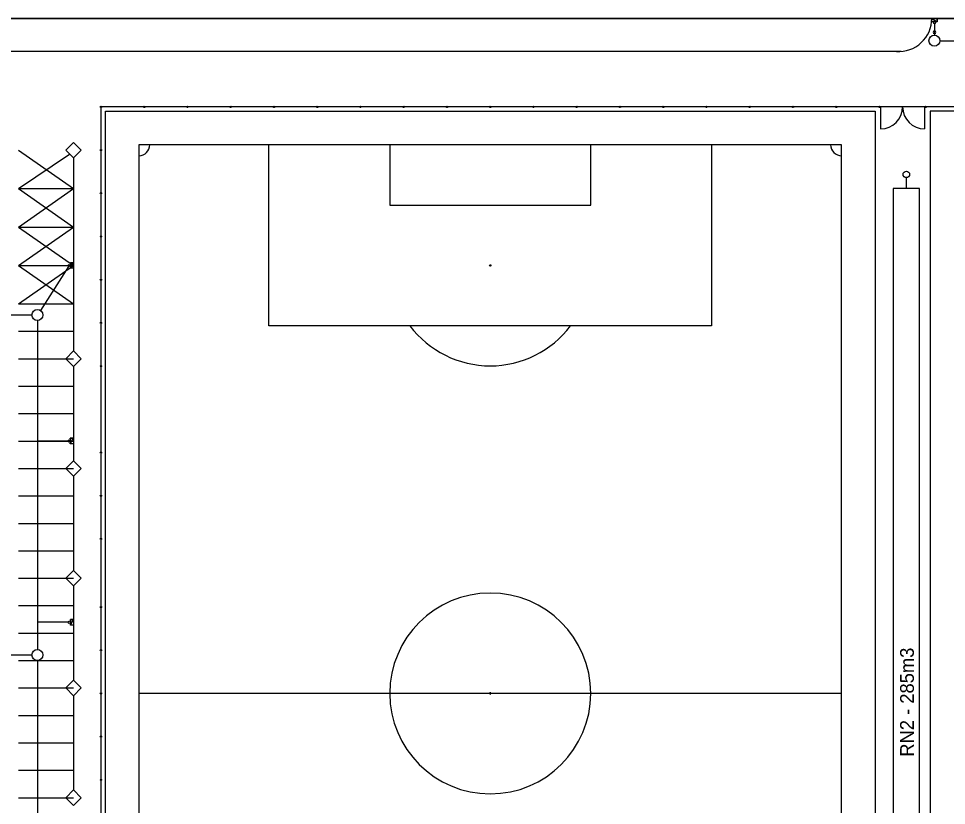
# Model space of a CAD drawing. Extents: x -264205 to -263615, y -1242401 to -1242031.
# Drawn here: x -264125.6 to -264041.1, y -1242251.2 to -1242179.5 of the extents above; entities that cross this region are included whole.
import ezdxf

# ---------------------------------------------------------------- set-up
doc = ezdxf.new("R2010")
doc.units = 0
doc.layers.add('KOORDINACNA_SITUACIA_DSP', color=7, linetype='Continuous')
doc.layers.add('PROJEKT_DRS_TDZ_VODOROVNE', color=7, linetype='Continuous')

msp = doc.modelspace()

# ---------------------------------------------------------------- linework, layer by layer
at = {"layer": 'KOORDINACNA_SITUACIA_DSP'}
for p, q in [((-264077.23, -1242179.482), (-264131.568, -1242179.482)), ((-264131.568, -1242179.482), (-263959.468, -1242179.482)), ((-263959.468, -1242179.482), (-264131.568, -1242179.482)), ((-263959.468, -1242179.482), (-264077.23, -1242179.482)), ((-264042.417, -1242179.482), (-264041.917, -1242179.482)), ((-264042.417, -1242179.772), (-264042.417, -1242179.482)), ((-264042.417, -1242179.482), (-264041.917, -1242179.772)), ((-264042.417, -1242179.482), (-264041.917, -1242179.772)), ((-264041.917, -1242179.482), (-264042.417, -1242179.482)), ((-264041.917, -1242179.482), (-264041.917, -1242179.772)), ((-264041.917, -1242179.772), (-264041.917, -1242179.482)), ((-264041.917, -1242179.772), (-264042.417, -1242179.772)), ((-264042.167, -1242179.972), (-264042.167, -1242181)), ((-264041.667, -1242181.5), (-264014.161, -1242181.5)), ((-264045.204, -1242182.482), (-264131.568, -1242182.482)), ((-264118.008, -1242187.532), (-264118.128, -1242187.532)), ((-264118.068, -1242187.592), (-264118.068, -1242187.472)), ((-263972.068, -1242187.532), (-264118.068, -1242187.532)), ((-264118.068, -1242187.532), (-264118.068, -1242294.432)), ((-264114.069, -1242187.532), (-264114.189, -1242187.532)), ((-264114.129, -1242187.592), (-264114.129, -1242187.472)), ((-264110.13, -1242187.532), (-264110.25, -1242187.532)), ((-264110.19, -1242187.592), (-264110.19, -1242187.472)), ((-264106.191, -1242187.532), (-264106.311, -1242187.532)), ((-264106.251, -1242187.592), (-264106.251, -1242187.472)), ((-264102.252, -1242187.532), (-264102.372, -1242187.532)), ((-264102.312, -1242187.592), (-264102.312, -1242187.472)), ((-264098.313, -1242187.532), (-264098.433, -1242187.532)), ((-264098.373, -1242187.592), (-264098.373, -1242187.472)), ((-264094.374, -1242187.532), (-264094.494, -1242187.532)), ((-264094.434, -1242187.592), (-264094.434, -1242187.472)), ((-264090.436, -1242187.532), (-264090.556, -1242187.532)), ((-264090.496, -1242187.592), (-264090.496, -1242187.472)), ((-264086.497, -1242187.532), (-264086.617, -1242187.532)), ((-264086.557, -1242187.592), (-264086.557, -1242187.472)), ((-264082.558, -1242187.532), (-264082.678, -1242187.532)), ((-264082.618, -1242187.592), (-264082.618, -1242187.472)), ((-264078.619, -1242187.532), (-264078.739, -1242187.532)), ((-264078.679, -1242187.592), (-264078.679, -1242187.472)), ((-264074.68, -1242187.532), (-264074.8, -1242187.532)), ((-264074.74, -1242187.592), (-264074.74, -1242187.472)), ((-264070.741, -1242187.532), (-264070.861, -1242187.532)), ((-264070.801, -1242187.592), (-264070.801, -1242187.472)), ((-264066.802, -1242187.532), (-264066.922, -1242187.532)), ((-264066.862, -1242187.592), (-264066.862, -1242187.472)), ((-264062.863, -1242187.532), (-264062.983, -1242187.532)), ((-264062.923, -1242187.592), (-264062.923, -1242187.472)), ((-264058.924, -1242187.532), (-264059.044, -1242187.532)), ((-264058.984, -1242187.592), (-264058.984, -1242187.472)), ((-264054.986, -1242187.532), (-264055.106, -1242187.532)), ((-264055.046, -1242187.592), (-264055.046, -1242187.472)), ((-264051.047, -1242187.532), (-264051.167, -1242187.532)), ((-264051.107, -1242187.592), (-264051.107, -1242187.472)), ((-264047.108, -1242187.532), (-264047.228, -1242187.532)), ((-264047.168, -1242187.592), (-264047.168, -1242187.472)), ((-264047.068, -1242187.532), (-264047.068, -1242189.532)), ((-264044.568, -1242187.532), (-264045.568, -1242187.532)), ((-264043.068, -1242187.532), (-264043.068, -1242189.532)), ((-264042.908, -1242187.532), (-264043.028, -1242187.532)), ((-264042.968, -1242187.592), (-264042.968, -1242187.472)), ((-264118.068, -1242191.41), (-264118.068, -1242191.53)), ((-264050.618, -1242190.982), (-264114.618, -1242190.982)), ((-264114.618, -1242190.982), (-264114.618, -1242290.982)), ((-264102.778, -1242207.482), (-264102.778, -1242190.982)), ((-264091.778, -1242190.982), (-264091.778, -1242196.482)), ((-264073.458, -1242196.482), (-264073.458, -1242190.982)), ((-264062.458, -1242190.982), (-264062.458, -1242207.482)), ((-264050.618, -1242290.982), (-264050.618, -1242190.982)), ((-264120.568, -1242192.189), (-264120.568, -1242209.775)), ((-264118.008, -1242191.47), (-264118.128, -1242191.47)), ((-264044.727, -1242194.982), (-264044.727, -1242193.982)), ((-264118.008, -1242195.407), (-264118.128, -1242195.407)), ((-264118.068, -1242195.347), (-264118.068, -1242195.467)), ((-264043.527, -1242194.982), (-264045.927, -1242194.982)), ((-264045.927, -1242194.982), (-264045.927, -1242293.982)), ((-264043.527, -1242293.982), (-264043.527, -1242194.982)), ((-264091.778, -1242196.482), (-264073.458, -1242196.482)), ((-264118.008, -1242199.345), (-264118.128, -1242199.345)), ((-264118.068, -1242199.285), (-264118.068, -1242199.405)), ((-264121.012, -1242202.066), (-264123.585, -1242206.079)), ((-264120.858, -1242202.232), (-264120.858, -1242201.732)), ((-264120.858, -1242201.732), (-264120.568, -1242201.732)), ((-264120.858, -1242202.232), (-264120.568, -1242201.732)), ((-264120.858, -1242202.232), (-264120.568, -1242201.732)), ((-264120.568, -1242201.732), (-264120.858, -1242201.732)), ((-264120.858, -1242201.732), (-264120.858, -1242202.232)), ((-264120.568, -1242202.232), (-264120.858, -1242202.232)), ((-264120.568, -1242201.732), (-264120.568, -1242202.232)), ((-264118.068, -1242203.222), (-264118.068, -1242203.342)), ((-264118.008, -1242203.282), (-264118.128, -1242203.282)), ((-264176.824, -1242206.476), (-264124.354, -1242206.476)), ((-264123.854, -1242207), (-264123.854, -1242236.976)), ((-264118.008, -1242207.22), (-264118.128, -1242207.22)), ((-264118.068, -1242207.16), (-264118.068, -1242207.28)), ((-264062.458, -1242207.482), (-264102.778, -1242207.482)), ((-264120.568, -1242211.189), (-264120.568, -1242219.774)), ((-264118.008, -1242211.157), (-264118.128, -1242211.157)), ((-264118.068, -1242211.097), (-264118.068, -1242211.217)), ((-264121.058, -1242217.982), (-264123.854, -1242217.982)), ((-264120.86, -1242218.232), (-264120.86, -1242217.732)), ((-264120.86, -1242217.732), (-264120.57, -1242217.732)), ((-264120.86, -1242218.232), (-264120.57, -1242217.732)), ((-264120.86, -1242218.232), (-264120.57, -1242217.732)), ((-264120.57, -1242217.732), (-264120.86, -1242217.732)), ((-264120.86, -1242217.732), (-264120.86, -1242218.232)), ((-264120.57, -1242218.232), (-264120.86, -1242218.232)), ((-264120.57, -1242217.732), (-264120.57, -1242218.232)), ((-264118.008, -1242219.032), (-264118.128, -1242219.032)), ((-264118.068, -1242218.972), (-264118.068, -1242219.092)), ((-264120.568, -1242221.189), (-264120.568, -1242229.774)), ((-264118.008, -1242222.97), (-264118.128, -1242222.97)), ((-264118.068, -1242222.91), (-264118.068, -1242223.03)), ((-264118.008, -1242226.907), (-264118.128, -1242226.907)), ((-264118.068, -1242226.847), (-264118.068, -1242226.967)), ((-264120.568, -1242231.189), (-264120.568, -1242239.774)), ((-264118.008, -1242233.107), (-264118.128, -1242233.107)), ((-264118.068, -1242233.047), (-264118.068, -1242233.167)), ((-264121.058, -1242234.499), (-264123.854, -1242234.499)), ((-264120.858, -1242234.749), (-264120.858, -1242234.249)), ((-264120.858, -1242234.249), (-264120.568, -1242234.249)), ((-264120.858, -1242234.749), (-264120.568, -1242234.249)), ((-264120.858, -1242234.749), (-264120.568, -1242234.249)), ((-264120.568, -1242234.249), (-264120.858, -1242234.249)), ((-264120.858, -1242234.249), (-264120.858, -1242234.749)), ((-264120.568, -1242234.249), (-264120.568, -1242234.749)), ((-264120.568, -1242234.749), (-264120.858, -1242234.749)), ((-264118.008, -1242237.045), (-264118.128, -1242237.045)), ((-264118.068, -1242236.985), (-264118.068, -1242237.105)), ((-264154.318, -1242237.476), (-264124.354, -1242237.476)), ((-264123.854, -1242237.976), (-264123.854, -1242297.736)), ((-264120.568, -1242241.189), (-264120.568, -1242249.774)), ((-264118.008, -1242240.982), (-264118.128, -1242240.982)), ((-264118.068, -1242241.042), (-264118.068, -1242240.922)), ((-264050.618, -1242240.982), (-264114.618, -1242240.982)), ((-264118.008, -1242244.92), (-264118.128, -1242244.92)), ((-264118.068, -1242244.98), (-264118.068, -1242244.86)), ((-264118.008, -1242248.857), (-264118.128, -1242248.857)), ((-264118.068, -1242248.917), (-264118.068, -1242248.797))]:
    msp.add_line(p, q, dxfattribs=at)
for points in [[(-264117.668, -1242187.932), (-264047.568, -1242187.932), (-264047.568, -1242294.032), (-264117.668, -1242294.032)], [(-264042.568, -1242294.032), (-263972.468, -1242294.032), (-263972.468, -1242187.932), (-264042.568, -1242187.932)], [(-264120.568, -1242190.775), (-264119.861, -1242191.482), (-264120.568, -1242192.189), (-264121.275, -1242191.482)], [(-264120.568, -1242209.775), (-264119.861, -1242210.482), (-264120.568, -1242211.189), (-264121.275, -1242210.482)], [(-264120.568, -1242219.775), (-264119.861, -1242220.482), (-264120.568, -1242221.189), (-264121.275, -1242220.482)], [(-264120.568, -1242229.775), (-264119.861, -1242230.482), (-264120.568, -1242231.189), (-264121.275, -1242230.482)], [(-264120.568, -1242239.775), (-264119.861, -1242240.482), (-264120.568, -1242241.189), (-264121.275, -1242240.482)], [(-264120.568, -1242249.775), (-264119.861, -1242250.482), (-264120.568, -1242251.189), (-264121.275, -1242250.482)]]:
    msp.add_lwpolyline(points, close=True, dxfattribs=at)
for centre, radius in [((-264042.167, -1242179.872), 0.1), ((-264042.167, -1242181.5), 0.5), ((-264118.068, -1242187.532), 0.06), ((-264114.129, -1242187.532), 0.06), ((-264110.19, -1242187.532), 0.06), ((-264106.251, -1242187.532), 0.06), ((-264102.312, -1242187.532), 0.06), ((-264098.373, -1242187.532), 0.06), ((-264094.434, -1242187.532), 0.06), ((-264090.496, -1242187.532), 0.06), ((-264086.557, -1242187.532), 0.06), ((-264082.618, -1242187.532), 0.06), ((-264078.679, -1242187.532), 0.06), ((-264074.74, -1242187.532), 0.06), ((-264070.801, -1242187.532), 0.06), ((-264066.862, -1242187.532), 0.06), ((-264062.923, -1242187.532), 0.06), ((-264058.984, -1242187.532), 0.06), ((-264055.046, -1242187.532), 0.06), ((-264051.107, -1242187.532), 0.06), ((-264047.168, -1242187.532), 0.06), ((-264042.968, -1242187.532), 0.06), ((-264118.068, -1242191.47), 0.06), ((-264044.727, -1242193.682), 0.3), ((-264118.068, -1242195.407), 0.06), ((-264118.068, -1242199.345), 0.06), ((-264120.958, -1242201.982), 0.1), ((-264082.618, -1242201.982), 0.06), ((-264118.068, -1242203.282), 0.06), ((-264123.854, -1242206.5), 0.5), ((-264118.068, -1242207.22), 0.06), ((-264118.068, -1242211.157), 0.06), ((-264120.958, -1242217.982), 0.1), ((-264118.068, -1242219.032), 0.06), ((-264118.068, -1242222.97), 0.06), ((-264118.068, -1242226.907), 0.06), ((-264118.068, -1242233.107), 0.06), ((-264120.958, -1242234.499), 0.1), ((-264123.854, -1242237.476), 0.5), ((-264118.068, -1242237.045), 0.06), ((-264118.068, -1242240.982), 0.06), ((-264118.068, -1242244.92), 0.06), ((-264118.068, -1242248.857), 0.06)]:
    msp.add_circle(centre, radius, dxfattribs=at)
for centre, radius, start, end in [((-264045.412, -1242179.495), 2.994, 266.03136, 0.25001), ((-264042.167, -1242180.736), 0.125, 0, 180), ((-264042.167, -1242180.736), 0.125, 180, 0), ((-264047.068, -1242187.532), 2, 270, 360), ((-264043.068, -1242187.532), 2, 180, 270), ((-264114.618, -1242190.982), 1, 270, 360), ((-264050.618, -1242190.982), 1, 180, 270), ((-264082.618, -1242201.982), 0.0303, 90, 270), ((-264082.618, -1242201.982), 0.0303, 270, 90), ((-264082.618, -1242201.982), 9.15, 216.94821, 323.05179), ((-264082.618, -1242240.982), 9.15, 360, 180), ((-264082.618, -1242240.982), 9.15, 180, 360), ((-264082.618, -1242240.982), 0.0605, 90, 270), ((-264082.618, -1242240.982), 0.0605, 270, 90)]:
    msp.add_arc(centre, radius, start, end, dxfattribs=at)
at = {"layer": 'PROJEKT_DRS_TDZ_VODOROVNE'}
for p, q in [((-264125.568, -1242191.482), (-264120.568, -1242194.982)), ((-264125.568, -1242194.982), (-264120.921, -1242191.836)), ((-264125.568, -1242194.982), (-264120.568, -1242194.982)), ((-264125.568, -1242194.982), (-264120.568, -1242198.482)), ((-264125.568, -1242198.482), (-264120.568, -1242194.982)), ((-264125.568, -1242198.482), (-264120.568, -1242198.482)), ((-264125.568, -1242198.482), (-264120.568, -1242201.982)), ((-264125.568, -1242201.982), (-264120.568, -1242198.482)), ((-264125.568, -1242201.982), (-264120.568, -1242201.982)), ((-264125.568, -1242201.982), (-264120.568, -1242201.982)), ((-264125.568, -1242201.982), (-264120.568, -1242205.482)), ((-264125.568, -1242205.482), (-264120.568, -1242201.982)), ((-264125.568, -1242205.482), (-264120.568, -1242205.482)), ((-264125.568, -1242207.982), (-264120.568, -1242207.982)), ((-264125.568, -1242210.482), (-264120.568, -1242210.482)), ((-264125.568, -1242212.982), (-264120.568, -1242212.982)), ((-264125.568, -1242215.482), (-264120.568, -1242215.482)), ((-264125.568, -1242217.982), (-264120.568, -1242217.982)), ((-264125.568, -1242220.482), (-264120.568, -1242220.482)), ((-264125.568, -1242222.982), (-264120.568, -1242222.982)), ((-264125.568, -1242225.482), (-264120.568, -1242225.482)), ((-264125.568, -1242227.982), (-264120.568, -1242227.982)), ((-264125.568, -1242230.482), (-264120.568, -1242230.482)), ((-264125.568, -1242232.982), (-264120.568, -1242232.982)), ((-264125.568, -1242232.982), (-264120.568, -1242232.982)), ((-264125.568, -1242235.482), (-264120.568, -1242235.482)), ((-264125.568, -1242237.982), (-264120.568, -1242237.982)), ((-264125.568, -1242240.482), (-264120.568, -1242240.482)), ((-264125.568, -1242242.982), (-264120.568, -1242242.982)), ((-264125.568, -1242245.482), (-264120.568, -1242245.482)), ((-264125.568, -1242247.982), (-264120.568, -1242247.982)), ((-264125.568, -1242250.482), (-264120.568, -1242250.482))]:
    msp.add_line(p, q, dxfattribs=at)

# ---------------------------------------------------------------- texts
at = {"layer": 'KOORDINACNA_SITUACIA_DSP'}
msp.add_text('RN2 - 285m3', height=1.25, rotation=90, dxfattribs=at).set_placement((-264044.042, -1242246.747))

doc.saveas('drawing.dxf')
